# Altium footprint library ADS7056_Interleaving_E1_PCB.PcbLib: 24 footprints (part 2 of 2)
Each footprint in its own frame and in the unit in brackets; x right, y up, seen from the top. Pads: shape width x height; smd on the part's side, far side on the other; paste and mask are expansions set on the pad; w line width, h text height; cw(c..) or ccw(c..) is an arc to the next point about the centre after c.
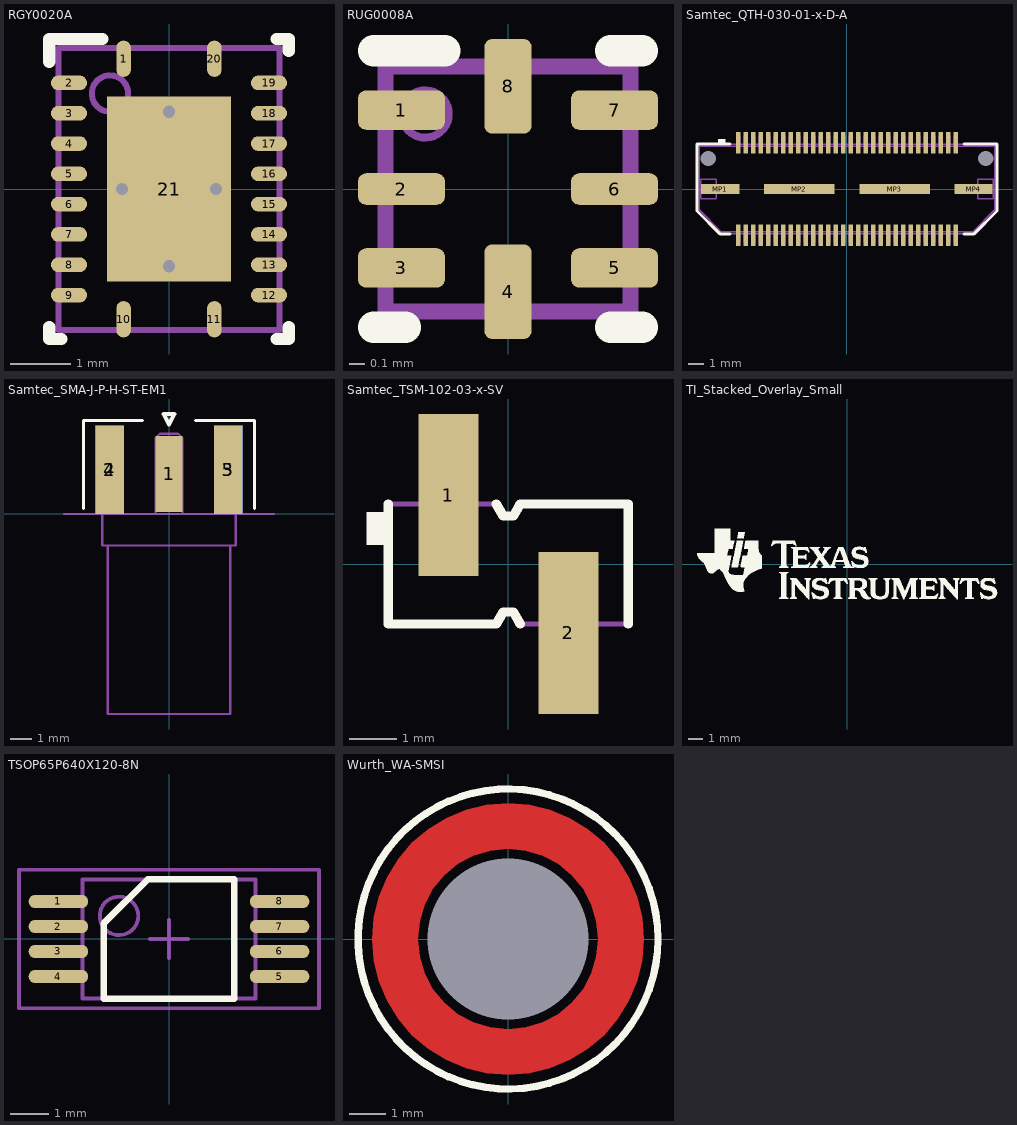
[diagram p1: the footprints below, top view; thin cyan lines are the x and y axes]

## RGY0020A [mm] "QFN, 20-Leads, Body 4.5x3.5mm, Pitch 0.5mm, Thermal Pad 3.05x2.05mm, TI Recommended"
height 1
pads (21):
  oval 0.24x0.6 smd: 1(-0.75,2.15) 10(-0.75,-2.15) 11(0.75,-2.15) 20(0.75,2.15)
  oval 0.6x0.24 smd: 2(-1.65,1.75) 3(-1.65,1.25) 4(-1.65,0.75) 5(-1.65,0.25) 6(-1.65,-0.25) 7(-1.65,-0.75) 8(-1.65,-1.25) 9(-1.65,-1.75) 12(1.65,-1.75) 13(1.65,-1.25) 14(1.65,-0.75) 15(1.65,-0.25) 16(1.65,0.25) 17(1.65,0.75) 18(1.65,1.25) 19(1.65,1.75)
  rect 2.05x3.05 smd paste-1.025: 21(0,0)
via 0.775,0 diameter 0.5 hole 0.2
via 0,-1.275 diameter 0.5 hole 0.2
via -0.775,0 diameter 0.5 hole 0.2
via 0,1.275 diameter 0.5 hole 0.2
Top Overlay:
  lines w0.2: -1.975,-2.275 -1.975,-2.475 -1.775,-2.475 ; -1.975,2.1 -1.975,2.475 -1.1,2.475 ; 1.775,-2.475 1.975,-2.475 1.975,-2.275 ; 1.775,2.475 1.975,2.475 1.975,2.275
Top Paste:
  rectangle: 0.1,-1.428 1.017,-0.1
  region: -0.1,-0.1 -1.017,-0.1 -1.017,-1.428 -0.1,-1.428
  region: -0.1,1.428 -1.017,1.428 -1.017,0.1 -0.1,0.1
  rectangle: 0.1,0.1 1.017,1.428
Mechanical 5:
  circle w0.1: c-0.975,1.575 r0.3
  lines w0.1: -1.825,-2.325 -1.825,2.325 1.825,2.325 1.825,-2.325 -1.825,-2.325
  text ".Designator" at -1.397,-0.635 h0.76
3D body "RGY0020A.stp": height 1, standoff 0, extent -1.75,-2.25 1.75,2.25

## RUG0008A [mm] "QFN, 8-Leads, Body 1.5x1.5mm, Pitch 0.5mm, TI Recommended"
height 0.4
pads (8):
  rrect40% 0.55x0.25 smd: 1(-0.675,0.5) 3(-0.675,-0.5) 5(0.675,-0.5) 7(0.675,0.5)
  rrect50% 0.55x0.2 smd: 2(-0.675,0) 6(0.675,0)
  rrect33% 0.3x0.6 smd: 4(0,-0.65) 8(0,0.65)
Top Overlay:
  lines w0.2: -0.85,-0.875 -0.65,-0.875 ; -0.85,0.875 -0.4,0.875 ; 0.65,-0.875 0.85,-0.875 ; 0.65,0.875 0.85,0.875
Mechanical 5:
  circle w0.05: c-0.525,0.475 r0.15
  lines w0.1: -0.775,-0.775 0.775,-0.775 0.775,0.775 -0.775,0.775 -0.775,-0.775
  text ".Designator" at -0.635,-0.254 h0.36
3D body: height 0.41, standoff 0.2, extent -0.674,0.326 -0.376,0.624
3D body: height 0.4, standoff 0, extent -0.775,-0.775 0.775,0.775

## Samtec_QTH-030-01-x-D-A [mil] "Header (Shrouded), 19.7mil, 30x2, SMT"
height 162
pads (66):
  rect 12x57 smd: 1(-285.7,121.5) 2(-285.7,-121.5) 3(-266,121.5) 4(-266,-121.5) 5(-246.3,121.5) 6(-246.3,-121.5) 7(-226.6,121.5) 8(-226.6,-121.5) 9(-206.9,121.5) 10(-206.9,-121.5) 11(-187.2,121.5) 12(-187.2,-121.5) 13(-167.5,121.5) 14(-167.5,-121.5) 15(-147.8,121.5) 16(-147.8,-121.5) 17(-128.1,121.5) 18(-128.1,-121.5) 19(-108.4,121.5) 20(-108.4,-121.5) 21(-88.7,121.5) 22(-88.7,-121.5) 23(-69,121.5) 24(-69,-121.5) 25(-49.3,121.5) 26(-49.3,-121.5) 27(-29.6,121.5) 28(-29.6,-121.5) 29(-9.9,121.5) 30(-9.9,-121.5) 31(9.8,121.5) 32(9.8,-121.5) 33(29.5,121.5) 34(29.5,-121.5) 35(49.2,121.5) 36(49.2,-121.5) 37(68.9,121.5) 38(68.9,-121.5) 39(88.6,121.5) 40(88.6,-121.5) 41(108.3,121.5) 42(108.3,-121.5) 43(128,121.5) 44(128,-121.5) 45(147.7,121.5) 46(147.7,-121.5) 47(167.4,121.5) 48(167.4,-121.5) 49(187.1,121.5) 50(187.1,-121.5) 51(206.8,121.5) 52(206.8,-121.5) 53(226.5,121.5) 54(226.5,-121.5) 55(246.2,121.5) 56(246.2,-121.5) 57(265.9,121.5) 58(265.9,-121.5) 59(285.6,121.5) 60(285.6,-121.5)
  round 0 hole 40 unplated: MH1(-364,80) MH2(364,80)
  rect 100x25 smd: MP1(-332.7,0) MP4(332.3,0)
  rect 185x25 smd: MP2(-125.2,0) MP3(124.8,0)
Top Overlay:
  rectangle: -338.67,118.11 -318.9,131.28
  lines w7.87: -307,-117.5 -333.75,-117.5 -393.75,-57.5 -393.75,20 -393.75,117.5 -307,117.5 ; 307,-117.5 333.75,-117.5 393.75,-57.5 393.75,20 393.75,117.5 307,117.5
Mechanical 5:
  drawing of 212 lines, arcs and shapes, not listed
  text ".Designator" at -118.11,-11.33 h40
3D body "Samtec-QTH-030-01-L-D-A.stp": height 170.01, standoff -27, extent -393.75,-140 393.75,140

## Samtec_SMA-J-P-H-ST-EM1 [mm] "SMA Jack, R/A, SMT"
height 3.68
pads (5):
  rect 1.27x3.6 smd: 1(0,1.9)
  rect 1.35x4.2 smd: 2(-2.825,2.1) 3(2.825,2.1)
  rect 1.35x4.2 smd far side: 4(-2.825,2.1) 5(2.825,2.1)
Top Overlay:
  lines w0.152: -4.064,0.254 -4.064,4.445 -1.27,4.445 ; 1.27,4.445 4.064,4.445 4.064,0.254
  lines w0.2: -0.25,4.75 0,4.25 0.25,4.75 -0.25,4.75
Mechanical 1:
  lines w0.1: -5,0 5,0
Mechanical 5:
  lines w0.1: -2.915,-1.5 -2.915,-9.52 2.915,-9.52 2.915,-1.5 ; -2.365,0 -2.365,3.81 -3.175,3.81 -3.175,0 ; -0.635,0 -0.635,3.61 ; 0.635,0 0.635,3.61 ; 2.365,0 2.365,3.81 3.175,3.81 3.175,0 ; -3.175,0 3.175,0 ; -3.175,0 -3.175,-1.5 0,-1.5 3.175,-1.5 3.175,0 ; -0.635,3.61 0.635,3.61 ; -0.635,3.61 -0.435,3.81 0.435,3.81 0.635,3.61
  text ".Designator" at -1.25,-1.25 h1.02
3D body "SMA-J-P-H-ST-EM1.stp": height 3.8, standoff -2.8, extent -3.175,-9.52 3.175,3.81

## Samtec_TSM-102-03-x-SV [mm] "Header, 2.54mm, 2x1, SMT"
height 14.99
pads (2):
  rect 1.27x3.43 smd: 1(-1.27,1.46) 2(1.27,-1.46)
Top Overlay:
  rectangle: -3,0.4 -2.54,1.1
  lines w0.2: -2.54,1.27 -2.54,-1.27 -0.254,-1.27 -0.107,-1.016 0.107,-1.016 0.254,-1.27 ; -0.254,1.27 -0.107,1.016 0.107,1.016 0.254,1.27 2.54,1.27 2.54,-1.27
Mechanical 5:
  lines w0.1: -1.587,1.27 -1.587,2.603 -0.953,2.603 -0.953,1.27 ; 0.953,-1.27 0.953,-2.604 1.587,-2.604 1.587,-1.27 ; -2.54,-1.27 -2.54,1.27 -0.254,1.27 -0.107,1.016 0.107,1.016 0.254,1.27 2.54,1.27 2.54,-1.27 0.254,-1.27 0.107,-1.016 -0.107,-1.016 -0.254,-1.27 -2.54,-1.27
  text ".Designator" at -1.524,-0.508 h1.02
3D body "TSM-102-03-T-SV.stp": height 14.48, standoff 0, extent -2.54,-2.603 2.54,2.604

## TI_Stacked_Overlay_Small [mm]
Top Overlay:
  drawing of 18 lines, arcs and shapes, not listed

## TSOP65P640X120-8N [mm] "TSOP, 8-Leads, Body 3.1x4.5mm (max), Pitch 0.65mm, IPC Medium Density"
height 1.2
pads (8):
  oval 1.55x0.35 smd mask+0.08: 1(-2.875,0.975) 2(-2.875,0.325) 3(-2.875,-0.325) 4(-2.875,-0.975) 5(2.875,-0.975) 6(2.875,-0.325) 7(2.875,0.325) 8(2.875,0.975)
Top Overlay:
  lines w0.17: -1.7,-1.55 1.7,-1.55 1.7,1.55 -0.55,1.55 -1.7,0.4 -1.7,-1.55
Mechanical 5:
  circle w0.1: c-1.3,0.6 r0.5
  lines w0.1: -2.25,-1.55 2.25,-1.55 2.25,1.55 -2.25,1.55 -2.25,-1.55
  text ".Designator" at -1.8,-1.2 h1
Mechanical 15:
  lines w0.1: -0.5,0 0.5,0 ; 0,-0.5 0,0.5 ; -3.9,-1.8 3.9,-1.8 3.9,1.8 -3.9,1.8 -3.9,-1.8
3D body: height 1.2, standoff 0.15, extent -2.25,-1.55 2.25,1.55
3D body: height 1.21, standoff 1, extent -1.799,0.101 -0.801,1.099

## Wurth_WA-SMSI [mm] "ROUND STANDOFF M3 STEEL 5MM"
height 5
pads (1):
  round 0 hole 4.4 unplated: ""(0,0)
Top Layer:
  region: -3.711,0 -3.666,-0.581 -3.53,-1.147 -3.307,-1.685 -3.003,-2.182 -2.624,-2.624 -2.182,-3.003 -1.685,-3.307 -1.147,-3.53 -0.581,-3.666 0,-3.711 0.581,-3.666 1.147,-3.53 1.685,-3.307 2.182,-3.003 2.624,-2.624 3.003,-2.182 3.307,-1.685 3.53,-1.147 3.666,-0.581 3.711,0 3.7,0 2.466,0 2.418,-0.481 2.278,-0.944 2.05,-1.37 1.744,-1.744 1.37,-2.05 0.944,-2.278 0.481,-2.418 0,-2.466 -0.481,-2.418 -0.944,-2.278 -1.37,-2.05 -1.744,-1.744 -2.05,-1.37 -2.278,-0.944 -2.418,-0.481 -2.466,0 -2.454,0
  region: -3.711,0 -3.666,0.581 -3.53,1.147 -3.307,1.685 -3.003,2.182 -2.624,2.624 -2.182,3.003 -1.685,3.307 -1.147,3.53 -0.581,3.666 0,3.711 0.581,3.666 1.147,3.53 1.685,3.307 2.182,3.003 2.624,2.624 3.003,2.182 3.307,1.685 3.53,1.147 3.666,0.581 3.711,0 3.7,0 2.466,0 2.418,0.481 2.278,0.944 2.05,1.37 1.744,1.744 1.37,2.05 0.944,2.278 0.481,2.418 0,2.466 -0.481,2.418 -0.944,2.278 -1.37,2.05 -1.744,1.744 -2.05,1.37 -2.278,0.944 -2.418,0.481 -2.466,0 -2.454,0
Top Overlay:
  circle w0.2: c0,0 r4.1
Top Paste:
  region: 2.184,-0.268 2.154,-0.448 2.05,-0.797 1.891,-1.125 1.679,-1.421 1.421,-1.679 1.125,-1.891 0.797,-2.05 0.448,-2.154 0.268,-2.184 0.268,-3.686 0.268,-3.69 0.488,-3.674 0.92,-3.591 1.339,-3.456 1.739,-3.273 2.114,-3.044 2.46,-2.772 2.771,-2.461 3.044,-2.115 3.273,-1.74 3.456,-1.34 3.59,-0.921 3.674,-0.489 3.69,-0.27 3.67,-0.268
  region: -0.268,-2.184 -0.448,-2.154 -0.797,-2.05 -1.125,-1.891 -1.421,-1.679 -1.679,-1.421 -1.891,-1.125 -2.05,-0.797 -2.154,-0.448 -2.184,-0.268 -3.686,-0.268 -3.69,-0.268 -3.674,-0.488 -3.591,-0.92 -3.456,-1.339 -3.273,-1.739 -3.044,-2.114 -2.772,-2.46 -2.461,-2.771 -2.115,-3.044 -1.74,-3.273 -1.34,-3.456 -0.921,-3.59 -0.489,-3.674 -0.27,-3.69 -0.268,-3.67
  region: -2.184,0.268 -2.154,0.448 -2.05,0.797 -1.891,1.125 -1.679,1.421 -1.421,1.679 -1.125,1.891 -0.797,2.05 -0.448,2.154 -0.268,2.184 -0.268,3.686 -0.268,3.69 -0.488,3.674 -0.92,3.591 -1.339,3.456 -1.739,3.273 -2.114,3.044 -2.46,2.772 -2.771,2.461 -3.044,2.115 -3.273,1.74 -3.456,1.34 -3.59,0.921 -3.674,0.489 -3.69,0.27 -3.67,0.268
  region: 0.268,2.184 0.448,2.154 0.797,2.05 1.125,1.891 1.421,1.679 1.679,1.421 1.891,1.125 2.05,0.797 2.154,0.448 2.184,0.268 3.686,0.268 3.69,0.268 3.674,0.488 3.591,0.92 3.456,1.339 3.273,1.739 3.044,2.114 2.772,2.46 2.461,2.771 2.115,3.044 1.74,3.273 1.34,3.456 0.921,3.59 0.489,3.674 0.27,3.69 0.268,3.67
Mechanical 5:
  circle w0.1: c0,0 r3
  text ".Designator" at -1.524,-0.508 h1.02
3D body "9774050360R.stp": height 5, standoff -1.4, extent -2.994,-2.976 2.994,3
